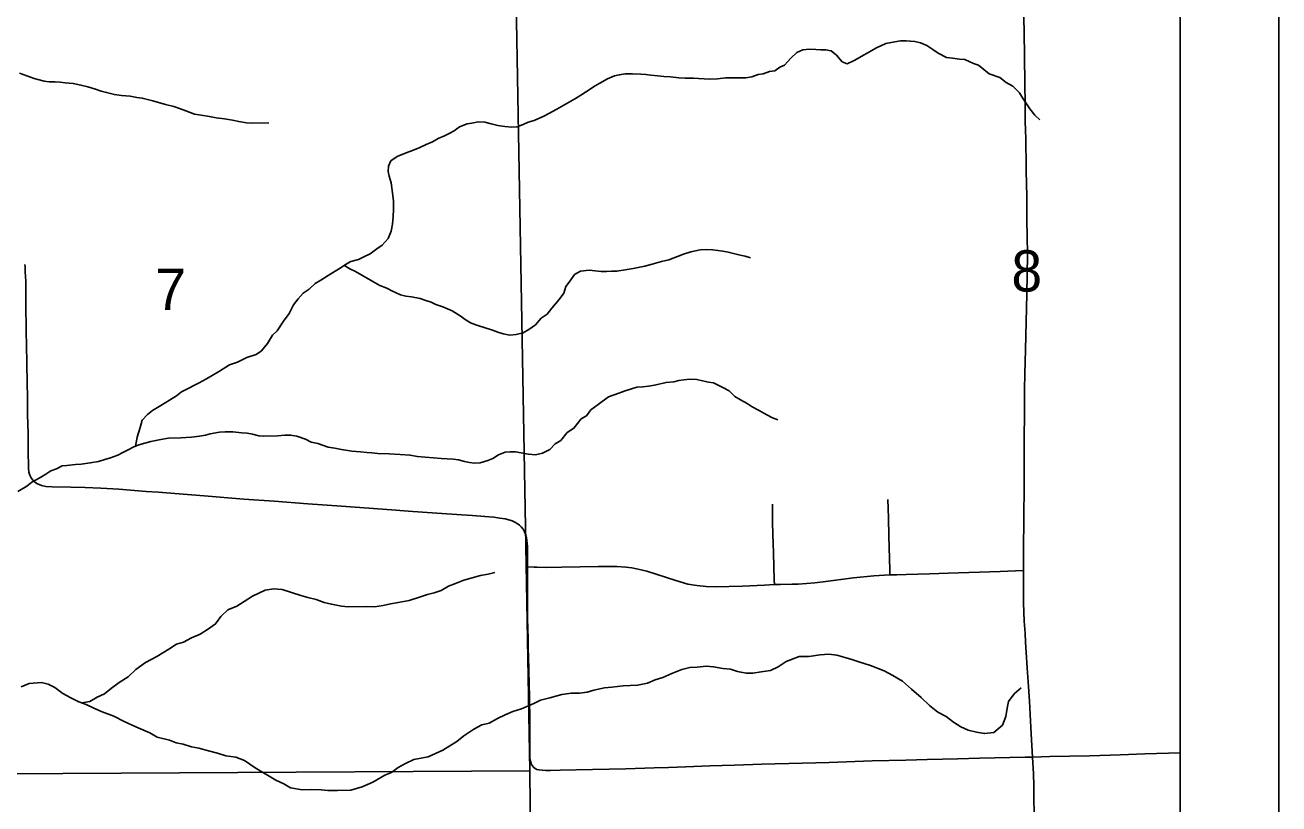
# Model space of a CAD drawing. Extents: x 0 to 34, y 0 to 22.
# Drawn here: x 23.486 to 24.758, y 12.591 to 13.381 of the extents above; entities that cross this region are included whole.
import ezdxf

# ---------------------------------------------------------------- set-up
doc = ezdxf.new("R2010")
doc.units = 0
for name, color, linetype in [('GM_X_Minor_River', 7, 'Continuous'), ('GM_X_Section', 7, 'Continuous'), ('GM_X_Section_Text', 7, 'Continuous'), ('GM_X_Township_Road', 7, 'Continuous'), ('SH_Data', 7, 'Continuous')]:
    doc.layers.add(name, color=color, linetype=linetype)

msp = doc.modelspace()

# ---------------------------------------------------------------- linework, layer by layer
at = {"layer": 'GM_X_Minor_River'}
for points in [[(24.1885, 13.3265), (24.1969, 13.3274), (24.2053, 13.3274), (24.211, 13.3275), (24.2174, 13.3275), (24.2235, 13.3283), (24.2296, 13.3307), (24.2349, 13.3315), (24.2413, 13.3338), (24.2467, 13.3346), (24.2516, 13.3381), (24.2565, 13.3404), (24.2629, 13.3473), (24.2689, 13.353), (24.275, 13.3557), (24.2814, 13.3566), (24.2883, 13.3562), (24.2932, 13.3559), (24.2982, 13.3559), (24.3039, 13.3548), (24.3093, 13.3503), (24.315, 13.3435), (24.32, 13.3417), (24.3272, 13.3451), (24.3499, 13.3579), (24.3593, 13.3621), (24.3647, 13.3633), (24.3742, 13.3649), (24.3799, 13.365), (24.3886, 13.3643), (24.3943, 13.3628), (24.4008, 13.3602), (24.4069, 13.3561), (24.4123, 13.3523), (24.4207, 13.3482), (24.4268, 13.3475), (24.434, 13.3464), (24.4393, 13.3461), (24.4481, 13.342), (24.4531, 13.3401), (24.4642, 13.3314), (24.4749, 13.3277), (24.4814, 13.3228), (24.4879, 13.3191), (24.4948, 13.3123), (24.4978, 13.307), (24.5013, 13.3021), (24.5052, 13.296), (24.5105, 13.2896), (24.5155, 13.2847)], [(23.4805, 13.3321), (23.4881, 13.3295), (23.4954, 13.3266), (23.5057, 13.324), (23.5106, 13.3233), (23.5167, 13.3233), (23.522, 13.323), (23.527, 13.3223), (23.535, 13.3216), (23.543, 13.3201), (23.5498, 13.3183), (23.5578, 13.316), (23.5636, 13.3138), (23.5689, 13.3127), (23.5769, 13.3105), (23.5841, 13.3094), (23.5929, 13.3087), (23.5997, 13.3076), (23.6051, 13.3069), (23.6157, 13.304), (23.6287, 13.3003), (23.6371, 13.2984), (23.6428, 13.2962), (23.6493, 13.294), (23.658, 13.2906), (23.6649, 13.2895), (23.6733, 13.2881), (23.6801, 13.287), (23.6885, 13.2859), (23.6965, 13.2845), (23.703, 13.283), (23.711, 13.2819), (23.7163, 13.2816), (23.7334, 13.2817)], [(23.5983, 12.9538), (23.6, 12.9631), (23.603, 12.9727), (23.6052, 12.9803), (23.6104, 12.986), (23.6154, 12.9902), (23.6241, 12.9953), (23.6328, 13.0007), (23.6399, 13.0049), (23.6448, 13.0091), (23.6524, 13.0126), (23.6581, 13.0157), (23.663, 13.018), (23.6702, 13.0223), (23.6835, 13.03), (23.6937, 13.0365), (23.7016, 13.0392), (23.7111, 13.0439), (23.7206, 13.047), (23.7259, 13.0505), (23.7323, 13.0581), (23.7371, 13.0665), (23.742, 13.0708), (23.7484, 13.0807), (23.7541, 13.0884), (23.7585, 13.0971), (23.7634, 13.1033), (23.7683, 13.109), (23.7744, 13.1132), (23.7804, 13.119), (23.7861, 13.1221), (23.7937, 13.1271), (23.8008, 13.1313), (23.8058, 13.1344), (23.8111, 13.1382), (23.8167, 13.1413), (23.8243, 13.1433), (23.83, 13.146), (23.8364, 13.1491), (23.8429, 13.1541), (23.8485, 13.1576), (23.8546, 13.1645), (23.8575, 13.1721), (23.859, 13.179), (23.8597, 13.1866), (23.86, 13.1942), (23.8599, 13.2022), (23.8591, 13.2082), (23.8575, 13.2211), (23.8555, 13.2276), (23.8544, 13.2325), (23.8547, 13.2379), (23.8573, 13.2432), (23.8637, 13.2478), (23.8728, 13.2513), (23.8793, 13.2536), (23.8865, 13.2567), (23.8929, 13.2598), (23.8994, 13.2626), (23.9054, 13.266), (23.9115, 13.2687), (23.9164, 13.2711), (23.9213, 13.2738), (23.927, 13.2776), (23.9346, 13.2807), (23.9395, 13.2815), (23.9459, 13.2827), (23.9524, 13.2824), (23.9589, 13.2809), (23.9658, 13.2791), (23.973, 13.278), (23.9798, 13.2773), (23.9855, 13.2777), (23.9916, 13.28), (23.9965, 13.2824), (24.0026, 13.2843), (24.0124, 13.2886), (24.0174, 13.2913), (24.0257, 13.2955), (24.0446, 13.3063), (24.0499, 13.3098), (24.0548, 13.3129), (24.0643, 13.3194), (24.0692, 13.3221), (24.0768, 13.3264), (24.084, 13.3295), (24.0889, 13.3303), (24.095, 13.3315), (24.1022, 13.3315), (24.1109, 13.3312), (24.1159, 13.3309), (24.1208, 13.3302), (24.1281, 13.3294), (24.1342, 13.3287), (24.141, 13.3284), (24.1494, 13.3273), (24.1558, 13.327), (24.1642, 13.3271), (24.1692, 13.3267), (24.1806, 13.3261), (24.1885, 13.3265)], [(23.8097, 13.1373), (23.8157, 13.1337), (23.8214, 13.1311), (23.8279, 13.1274), (23.839, 13.121), (23.8462, 13.1169), (23.8531, 13.1143), (23.8584, 13.1113), (23.8672, 13.1075), (23.8725, 13.1061), (23.8783, 13.1053), (23.887, 13.1035), (23.8927, 13.1017), (23.8981, 13.0998), (23.903, 13.0976), (23.9099, 13.0953), (23.9194, 13.0912), (23.9275, 13.086), (23.9336, 13.0818), (23.9386, 13.0788), (23.9454, 13.0762), (23.953, 13.074), (23.9603, 13.0714), (23.9656, 13.0695), (23.9713, 13.0677), (23.9778, 13.0666), (23.9843, 13.067), (23.9915, 13.069), (23.9972, 13.0721), (24.004, 13.0771), (24.0096, 13.0836), (24.0157, 13.0878), (24.0206, 13.094), (24.0281, 13.1028), (24.0326, 13.1089), (24.0348, 13.1157), (24.039, 13.1215), (24.0435, 13.128), (24.0495, 13.1315), (24.0583, 13.1323), (24.0643, 13.1316), (24.0704, 13.1312), (24.0758, 13.1309), (24.0811, 13.1313), (24.0864, 13.1314), (24.0948, 13.1326), (24.1031, 13.1342), (24.1096, 13.1354), (24.1149, 13.1366), (24.1221, 13.1385), (24.1316, 13.1412), (24.1392, 13.1428), (24.1479, 13.1463), (24.1539, 13.1487), (24.1615, 13.151), (24.171, 13.153), (24.1778, 13.1534), (24.1839, 13.1531), (24.1938, 13.1516), (24.1992, 13.1505), (24.206, 13.1491), (24.2114, 13.1476), (24.2167, 13.1465), (24.222, 13.145)], [(24.0557, 12.9847), (24.0602, 12.9908), (24.0674, 12.9962), (24.078, 13.0039), (24.0886, 13.0078), (24.095, 13.0101), (24.1068, 13.0137), (24.1129, 13.0141), (24.1186, 13.0149), (24.1246, 13.0157), (24.1364, 13.0185), (24.1444, 13.0193), (24.1493, 13.0205), (24.1543, 13.0213), (24.1603, 13.0217), (24.1676, 13.0214), (24.1733, 13.0203), (24.1794, 13.0188), (24.1843, 13.0181), (24.1931, 13.0136), (24.2004, 13.0099), (24.2061, 13.0042), (24.2118, 13.0008), (24.2187, 12.9971), (24.2237, 12.9937), (24.2302, 12.9903), (24.2386, 12.9858), (24.2443, 12.9828), (24.2497, 12.9806)], [(23.4788, 12.9081), (23.4879, 12.9132), (23.4932, 12.9174), (23.5007, 12.9216), (23.5072, 12.9255), (23.5124, 12.9289), (23.5181, 12.9309), (23.5238, 12.934), (23.5288, 12.9344), (23.5375, 12.9352), (23.5432, 12.9357), (23.5523, 12.9369), (23.5607, 12.9385), (23.5671, 12.9404), (23.5728, 12.942), (23.5804, 12.9447), (23.5853, 12.9474), (23.591, 12.9501), (23.5959, 12.9528), (23.6016, 12.9552), (23.6076, 12.9571), (23.6137, 12.9587), (23.619, 12.9595), (23.624, 12.9607), (23.6319, 12.9619), (23.6441, 12.9623), (23.6551, 12.9632), (23.6631, 12.964), (23.6692, 12.9652), (23.6741, 12.9664), (23.6836, 12.968), (23.6893, 12.9684), (23.6969, 12.9685), (23.706, 12.9674), (23.7114, 12.9671), (23.7171, 12.966), (23.7232, 12.9645), (23.7285, 12.9642), (23.7426, 12.9643), (23.7498, 12.9651), (23.7555, 12.9652), (23.762, 12.9641), (23.7707, 12.9611), (23.7765, 12.9581), (23.7833, 12.9566), (23.7936, 12.9529), (23.8005, 12.9518), (23.8073, 12.9504), (23.8176, 12.9489), (23.8264, 12.9482), (23.8328, 12.9475), (23.8378, 12.9472), (23.8442, 12.9465), (23.8557, 12.9462), (23.8667, 12.9455), (23.8766, 12.9449), (23.8842, 12.9434), (23.8922, 12.9427), (23.9006, 12.942), (23.9082, 12.9413), (23.9203, 12.9406), (23.9257, 12.9399), (23.9318, 12.9385), (23.9371, 12.9374), (23.942, 12.9366), (23.9477, 12.9371), (23.9557, 12.9394), (23.9606, 12.9414), (23.9663, 12.9452), (23.9731, 12.9479), (23.9784, 12.9483), (23.9838, 12.948), (23.9967, 12.9458), (24.0039, 12.9451), (24.0112, 12.9467), (24.0184, 12.9506), (24.024, 12.9563), (24.0297, 12.9598), (24.0361, 12.9678), (24.0429, 12.9721), (24.0504, 12.9816), (24.0557, 12.9847)], [(23.5438, 12.6935), (23.5521, 12.695), (23.5593, 12.6993), (23.5668, 12.7028), (23.574, 12.7085), (23.5816, 12.7143), (23.5907, 12.7201), (23.5986, 12.7274), (23.6084, 12.7347), (23.6198, 12.7405), (23.6322, 12.7482), (23.6398, 12.7532), (23.647, 12.7551), (23.655, 12.7594), (23.664, 12.7633), (23.6724, 12.7686), (23.6795, 12.7736), (23.6848, 12.7813), (23.692, 12.7878), (23.7011, 12.7917), (23.7086, 12.7963), (23.717, 12.8017), (23.7298, 12.8079), (23.7382, 12.8091), (23.7469, 12.8084), (23.766, 12.8025), (23.7732, 12.8003), (23.7816, 12.7984), (23.7896, 12.7955), (23.7969, 12.7936), (23.8072, 12.7918), (23.814, 12.7911), (23.8323, 12.7912), (23.8406, 12.7909), (23.8494, 12.7925), (23.8569, 12.7941), (23.8645, 12.7953), (23.8759, 12.7973), (23.8873, 12.8012), (23.8945, 12.8035), (23.9013, 12.8051), (23.9082, 12.8075), (23.9157, 12.8121), (23.9229, 12.8148), (23.9313, 12.8179), (23.9396, 12.8203), (23.9483, 12.8226), (23.9559, 12.8242), (23.9628, 12.8258)], [(23.4824, 12.71), (23.4903, 12.7132), (23.5029, 12.7144), (23.5097, 12.7126), (23.5166, 12.7092), (23.5246, 12.7032), (23.5327, 12.6987), (23.5407, 12.6946), (23.5483, 12.692), (23.5559, 12.6882), (23.5643, 12.6845), (23.5762, 12.68), (23.5869, 12.6748), (23.5987, 12.6692), (23.6128, 12.6632), (23.6201, 12.6587), (23.6326, 12.6558), (23.6395, 12.6532), (23.6467, 12.6517), (23.6551, 12.6491), (23.6624, 12.6476), (23.6723, 12.6451), (23.6814, 12.6425), (23.6898, 12.6399), (23.7001, 12.6384), (23.7089, 12.6351), (23.7196, 12.6276), (23.7406, 12.6152), (23.7486, 12.6115), (23.7555, 12.6073), (23.7673, 12.6055), (23.7772, 12.6056), (23.7867, 12.6053), (23.7935, 12.6046), (23.803, 12.6047), (23.8167, 12.6052), (23.8281, 12.6083), (23.8391, 12.6133), (23.8512, 12.6203), (23.858, 12.623), (23.8648, 12.628), (23.872, 12.6322), (23.8807, 12.6361), (23.8951, 12.6389), (23.9099, 12.6455), (23.9243, 12.6543), (23.9311, 12.6601), (23.9413, 12.667), (23.9496, 12.6713), (23.9568, 12.6729), (23.9655, 12.6779), (23.9731, 12.6814), (23.9811, 12.6848), (23.9898, 12.6876), (24.0023, 12.693), (24.0091, 12.6965), (24.0186, 12.6988), (24.0307, 12.702), (24.0402, 12.7036), (24.0486, 12.7033), (24.0562, 12.7045), (24.063, 12.7064), (24.074, 12.7088), (24.0812, 12.7096), (24.093, 12.7109), (24.0999, 12.7113), (24.1075, 12.7114), (24.1177, 12.7137), (24.1253, 12.7168), (24.1332, 12.7192), (24.1423, 12.7234), (24.1522, 12.7273), (24.1605, 12.7293), (24.1678, 12.7297), (24.1769, 12.7309), (24.1845, 12.7302), (24.194, 12.7284), (24.2016, 12.7277), (24.2089, 12.7255), (24.2176, 12.7237), (24.2245, 12.7237), (24.2328, 12.7249), (24.2423, 12.7265), (24.2499, 12.73), (24.2582, 12.7354), (24.2715, 12.7405), (24.281, 12.7405), (24.2927, 12.7422), (24.3015, 12.743), (24.3095, 12.7419), (24.3167, 12.7401), (24.3247, 12.7375), (24.332, 12.7353)], [(24.332, 12.7353), (24.3438, 12.7315), (24.3575, 12.726), (24.3663, 12.7215), (24.3762, 12.7155), (24.3854, 12.7075), (24.395, 12.6989), (24.4034, 12.691), (24.4119, 12.6842), (24.4203, 12.6797), (24.4279, 12.6741), (24.4352, 12.6692), (24.4428, 12.6658), (24.4512, 12.664), (24.4592, 12.6625), (24.4687, 12.6634), (24.4774, 12.671), (24.4811, 12.6798), (24.4822, 12.6882), (24.4836, 12.695), (24.4893, 12.7027), (24.4965, 12.7088)]]:
    msp.add_lwpolyline(points, dxfattribs=at)
at = {"layer": 'GM_X_Section'}
for points in [[(23.2745, 13.6253), (23.9802, 13.6328), (23.9982, 12.6247), (23.2872, 12.6207), (23.2871, 12.632)], [(23.2872, 12.6207), (23.9982, 12.6247), (24.0077, 11.623), (23.2983, 11.6235)]]:
    msp.add_lwpolyline(points, close=True, dxfattribs=at)
at = {"layer": 'GM_X_Township_Road'}
for points in [[(24.4988, 12.8279), (24.4988, 12.8384), (24.4993, 12.8912), (24.4994, 12.9039), (24.4995, 12.9233), (24.4995, 12.9375), (24.4996, 12.9515), (24.4997, 12.9687), (24.4998, 12.9801), (24.4998, 12.9962), (24.4999, 13.0028), (24.4999, 13.0117), (24.5003, 13.0272), (24.5008, 13.0521), (24.5014, 13.08), (24.5021, 13.1079), (24.5028, 13.1481), (24.5026, 13.1675), (24.5024, 13.1822), (24.5022, 13.2071), (24.5017, 13.233), (24.5015, 13.2455), (24.5013, 13.257), (24.5012, 13.2652), (24.501, 13.2746), (24.5009, 13.2778), (24.5007, 13.2802), (24.5004, 13.3008), (24.5002, 13.3218), (24.4999, 13.349), (24.4996, 13.3737), (24.4989, 13.4016)], [(23.4859, 13.1383), (23.4864, 13.1357), (23.4865, 13.1307), (23.4869, 13.1213), (23.487, 13.1079), (23.4872, 13.0916), (23.4873, 13.0778), (23.4875, 13.0697), (23.4877, 13.0564), (23.488, 13.038), (23.4884, 13.0179), (23.4886, 13.0041), (23.4889, 12.9901), (23.4889, 12.9858), (23.4895, 12.9672), (23.4895, 12.9454), (23.4897, 12.9361), (23.4898, 12.9316), (23.4901, 12.9274), (23.491, 12.9245), (23.4924, 12.9217), (23.494, 12.9194), (23.4961, 12.9174), (23.4989, 12.9156), (23.5029, 12.9141), (23.5075, 12.9131), (23.5139, 12.9127), (23.5327, 12.9125), (23.5473, 12.9121), (23.5631, 12.9112), (23.5813, 12.9102), (23.6091, 12.908), (23.6215, 12.9072), (23.6296, 12.9066)], [(23.6296, 12.9066), (23.6679, 12.9034), (23.7081, 12.9001), (23.739, 12.898), (23.7731, 12.8954), (23.8071, 12.8931), (23.835, 12.891), (23.8488, 12.89), (23.8623, 12.889), (23.8749, 12.8881), (23.8892, 12.8871), (23.904, 12.886), (23.9141, 12.8853), (23.9293, 12.8842), (23.9399, 12.8835), (23.9524, 12.8826), (23.9617, 12.8818), (23.9678, 12.881), (23.9731, 12.8802), (23.9768, 12.8793), (23.9803, 12.8782), (23.9831, 12.8769), (23.9853, 12.8756), (23.9877, 12.8739), (23.9895, 12.872), (23.9913, 12.8698), (23.9928, 12.8672), (23.994, 12.864), (23.9948, 12.8612), (23.9952, 12.8583), (23.9956, 12.8552), (23.9958, 12.8521), (23.9959, 12.8481), (23.9959, 12.8447), (23.9959, 12.8412), (23.996, 12.8369), (23.996, 12.8317)], [(24.2462, 12.8136), (24.246, 12.8181), (24.2453, 12.8458), (24.2446, 12.8643), (24.2444, 12.8767), (24.2443, 12.8859), (24.2442, 12.8951)], [(24.3634, 12.8233), (24.3633, 12.8285), (24.3623, 12.8626), (24.3618, 12.8813), (24.3612, 12.8999)], [(23.996, 12.8317), (23.9959, 12.8121), (23.9959, 12.8021), (23.9959, 12.7936), (23.996, 12.7883), (23.996, 12.7786), (23.9962, 12.7695), (23.9964, 12.7585), (23.9966, 12.7472), (23.9967, 12.7414), (23.9973, 12.726), (23.9979, 12.6993), (23.998, 12.6921), (23.9981, 12.6831), (23.9982, 12.6734), (23.9982, 12.664), (23.9982, 12.6526), (23.9982, 12.643), (23.9983, 12.6376), (23.9988, 12.6344), (23.9994, 12.6322), (24.0004, 12.6301), (24.0022, 12.628), (24.0035, 12.6271), (24.0053, 12.6261), (24.0075, 12.6256), (24.0107, 12.6252), (24.0143, 12.625), (24.0191, 12.6251), (24.0289, 12.6252), (24.0619, 12.626), (24.0956, 12.6267), (24.1243, 12.6277), (24.1389, 12.6282), (24.1563, 12.6288), (24.1808, 12.6296), (24.2056, 12.6304), (24.2335, 12.6314), (24.3019, 12.6332), (24.3454, 12.6347), (24.3795, 12.6356), (24.4013, 12.6362), (24.4324, 12.6369), (24.4541, 12.6376), (24.5007, 12.6386), (24.508, 12.6387)], [(23.996, 12.8317), (24.0026, 12.8313), (24.0058, 12.8311), (24.0151, 12.831), (24.0307, 12.8311), (24.0679, 12.8318), (24.0865, 12.8318), (24.0957, 12.8313), (24.1018, 12.8305), (24.1079, 12.8293), (24.1168, 12.8271), (24.1464, 12.8176), (24.1584, 12.8141), (24.1677, 12.8125), (24.177, 12.8115), (24.1864, 12.8112), (24.2138, 12.812), (24.2362, 12.8129), (24.2462, 12.8136)], [(24.2462, 12.8136), (24.2523, 12.8137), (24.2643, 12.8139), (24.2704, 12.8141), (24.2874, 12.8153), (24.2901, 12.8156), (24.2957, 12.8163), (24.3263, 12.8203), (24.3472, 12.8223), (24.3634, 12.8233)], [(24.3634, 12.8233), (24.3704, 12.8235), (24.3798, 12.8237), (24.4036, 12.8243), (24.4223, 12.8251), (24.4751, 12.8267), (24.4906, 12.8275), (24.4988, 12.8279)], [(24.508, 12.6387), (24.5067, 12.6621), (24.5056, 12.6819), (24.5048, 12.6952), (24.5037, 12.7148), (24.5027, 12.7291), (24.5017, 12.7448), (24.501, 12.755), (24.5004, 12.7642), (24.4997, 12.7765), (24.4989, 12.795), (24.4988, 12.8136), (24.4988, 12.8196), (24.4988, 12.8239), (24.4988, 12.8279)], [(24.508, 12.6387), (24.5256, 12.6391), (24.566, 12.6399), (24.597, 12.6409), (24.6219, 12.6418), (24.6579, 12.6428)], [(24.5099, 12.5659), (24.5095, 12.5969), (24.5092, 12.6099), (24.509, 12.6218), (24.508, 12.6387)]]:
    msp.add_lwpolyline(points, dxfattribs=at)
at = {"layer": 'SH_Data'}
for p, q in [((24.7579, 16.0775), (24.7579, 9.0775)), ((24.6579, 15.9775), (24.6579, 9.1775))]:
    msp.add_line(p, q, dxfattribs=at)

# ---------------------------------------------------------------- texts
at = {"layer": 'GM_X_Section_Text'}
for s, p in [('8', (24.4866, 13.1107)), ('7', (23.6183, 13.092))]:
    msp.add_text(s, height=0.0419, rotation=0, dxfattribs=at).set_placement(p)

doc.saveas('drawing.dxf')
